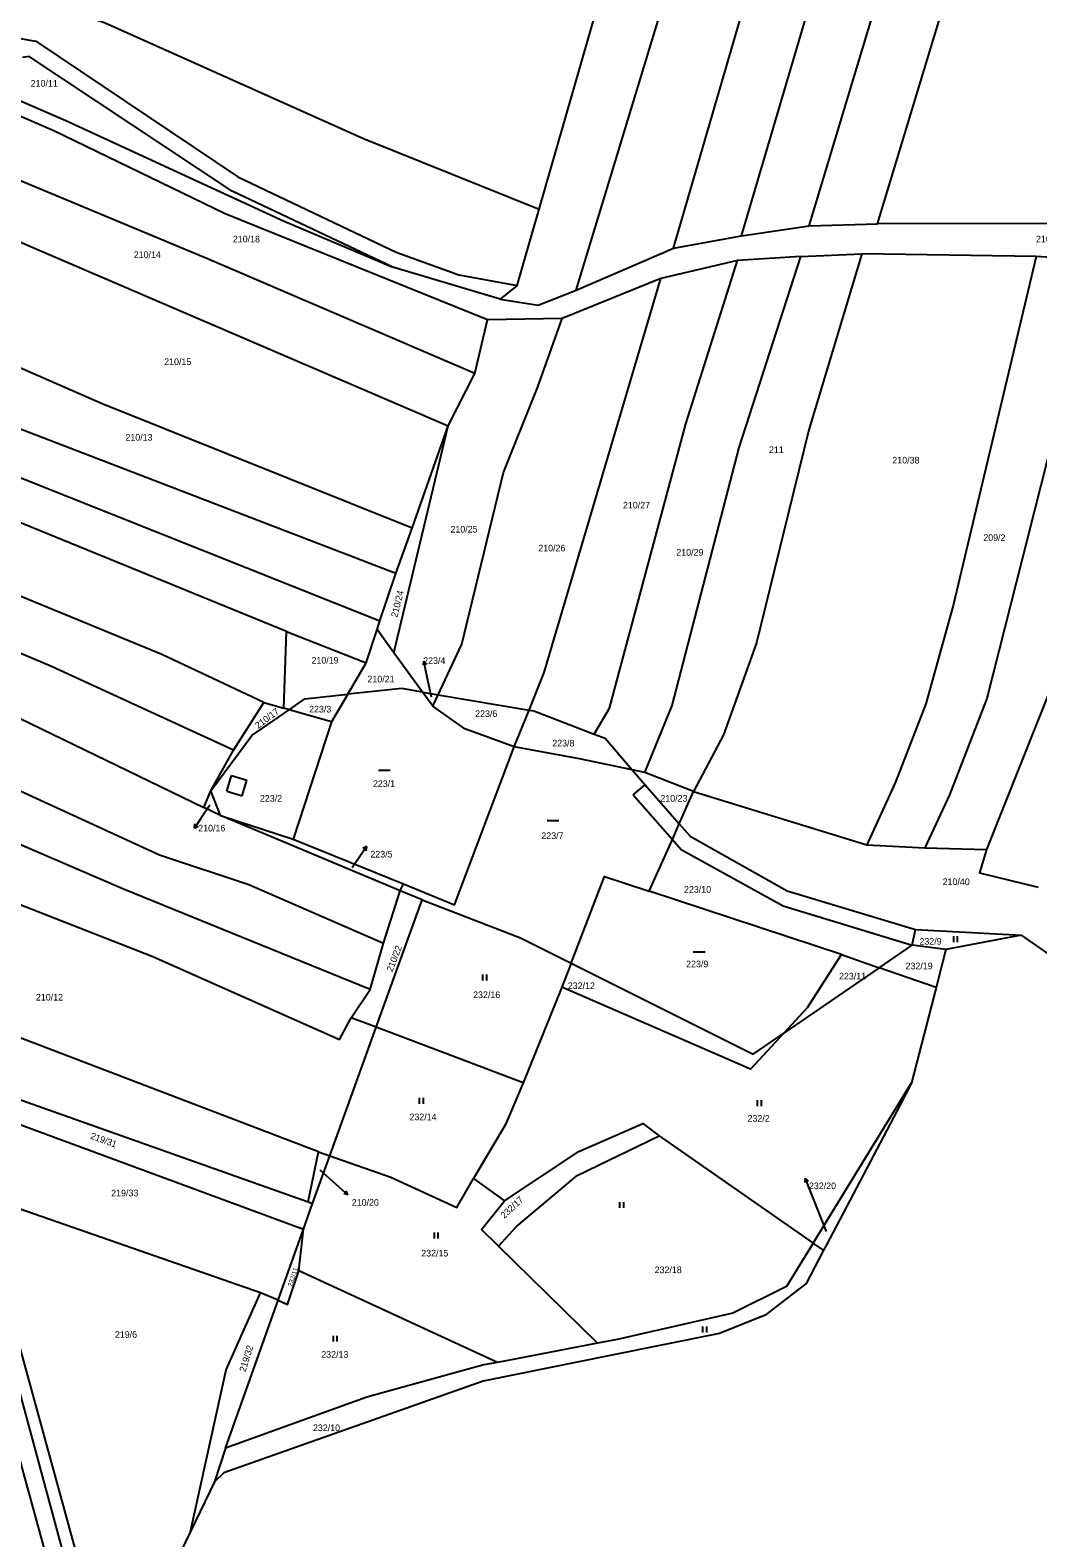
# Model space of a CAD drawing. Extents: x -744566 to -741843, y -1128407 to -1126744.
# Drawn here: x -742757.6 to -742498.8, y -1128024.5 to -1127637.5 of the extents above; entities that cross this region are included whole.
import ezdxf

# ---------------------------------------------------------------- set-up
doc = ezdxf.new("R2010")
doc.units = 0
for name, color, linetype in [('Hranice parcel', 7, 'Continuous'), ('Parcelní čísla', 7, 'Continuous'), ('Pop  PČ popisy', 7, 'Continuous'), ('Vnitřní kresba', 7, 'Continuous'), ('Značky kultur', 7, 'Continuous')]:
    doc.layers.add(name, color=color, linetype=linetype)

msp = doc.modelspace()

# ---------------------------------------------------------------- linework, layer by layer
at = {"layer": 'Hranice parcel'}
for p, q in [((-742626.86, -1127683.46), (-742607.54, -1127616.24)), ((-742632.48, -1127703.04), (-742626.86, -1127683.46)), ((-742574.91, -1127690.26), (-742557.53, -1127687.75)), ((-742557.53, -1127687.75), (-742539.98, -1127687.22)), ((-742494, -1127687.08), (-742539.98, -1127687.22)), ((-742592.33, -1127693.42), (-742574.91, -1127690.26)), ((-742617.34, -1127704.25), (-742592.33, -1127693.42)), ((-742559.67, -1127695.56), (-742575.9, -1127696.61)), ((-742559.67, -1127695.56), (-742544.01, -1127694.88)), ((-742499.23, -1127695.56), (-742544.01, -1127694.88)), ((-742483.38, -1127696.63), (-742499.23, -1127695.56)), ((-742636.82, -1127706.57), (-742664.42, -1127698.33)), ((-742575.9, -1127696.61), (-742595.59, -1127701.21)), ((-742632.48, -1127703.04), (-742636.82, -1127706.57)), ((-742595.59, -1127701.21), (-742620.93, -1127711.51)), ((-742643.36, -1127725.63), (-742640.13, -1127711.82)), ((-742620.93, -1127711.51), (-742640.13, -1127711.82)), ((-742650.2, -1127739.03), (-742643.36, -1127725.63)), ((-742663.65, -1127776.96), (-742792.35, -1127727.57)), ((-742664.19, -1127797.36), (-742650.2, -1127739.03)), ((-742659.43, -1127765.34), (-742650.2, -1127739.03)), ((-742663.65, -1127776.96), (-742659.43, -1127765.34)), ((-742667.79, -1127789.16), (-742663.65, -1127776.96)), ((-742692.45, -1127811.55), (-742691.75, -1127791.9)), ((-742691.75, -1127791.9), (-742671.24, -1127799.9)), ((-742671.24, -1127799.9), (-742668.48, -1127791.31)), ((-742668.48, -1127791.31), (-742667.79, -1127789.16)), ((-742664.19, -1127797.36), (-742668.48, -1127791.31)), ((-742675.99, -1127807.99), (-742671.24, -1127799.9)), ((-742656.82, -1127807.4), (-742664.19, -1127797.36)), ((-742675.99, -1127807.99), (-742680.15, -1127815.09)), ((-742656.82, -1127807.4), (-742652.76, -1127808.09)), ((-742654.13, -1127811.06), (-742656.82, -1127807.4)), ((-742654.13, -1127811.06), (-742652.76, -1127808.09)), ((-742652.76, -1127808.09), (-742629.43, -1127812.04)), ((-742705.33, -1127822.31), (-742697.57, -1127810.08)), ((-742697.57, -1127810.08), (-742692.45, -1127811.55)), ((-742691.07, -1127811.95), (-742692.45, -1127811.55)), ((-742680.15, -1127815.09), (-742691.07, -1127811.95)), ((-742633.23, -1127821.48), (-742629.43, -1127812.04)), ((-742680.15, -1127815.09), (-742690.04, -1127845.16)), ((-742711.14, -1127832.79), (-742705.33, -1127822.31)), ((-742599.71, -1127828.08), (-742602.93, -1127827.4)), ((-742587.17, -1127832.97), (-742599.71, -1127828.08)), ((-742712.92, -1127837.01), (-742711.14, -1127832.79)), ((-742708.67, -1127839.06), (-742711.14, -1127832.79)), ((-742590.87, -1127841.26), (-742587.17, -1127832.97)), ((-742587.17, -1127832.97), (-742542.71, -1127846.65)), ((-742708.67, -1127839.06), (-742712.92, -1127837.01)), ((-742662.54, -1127858.41), (-742708.67, -1127839.06)), ((-742708.67, -1127839.06), (-742690.04, -1127845.16)), ((-742690.04, -1127845.16), (-742661.69, -1127856.62)), ((-742542.71, -1127846.65), (-742527.8, -1127847.44)), ((-742527.8, -1127847.44), (-742511.96, -1127847.84)), ((-742666.84, -1127871.89), (-742662.54, -1127858.41)), ((-742662.54, -1127858.41), (-742661.69, -1127856.62)), ((-742656.86, -1127860.79), (-742662.54, -1127858.41)), ((-742549.19, -1127874.82), (-742598.57, -1127858.52)), ((-742668.67, -1127893.45), (-742656.86, -1127860.79)), ((-742531.05, -1127872.36), (-742530.23, -1127868.37)), ((-742530.23, -1127868.37), (-742503.01, -1127869.85)), ((-742503.01, -1127869.85), (-742522.38, -1127873.53)), ((-742491.5, -1127877.75), (-742503.01, -1127869.85)), ((-742670.28, -1127883.77), (-742666.84, -1127871.89)), ((-742539.51, -1127878.17), (-742531.05, -1127872.36)), ((-742522.38, -1127873.53), (-742531.05, -1127872.36)), ((-742522.38, -1127873.53), (-742524.88, -1127883.24)), ((-742618.61, -1127876.98), (-742620.99, -1127883.17)), ((-742549.19, -1127874.82), (-742539.51, -1127878.17)), ((-742539.51, -1127878.17), (-742564.03, -1127895.02)), ((-742524.88, -1127883.24), (-742539.51, -1127878.17)), ((-742675.1, -1127891.02), (-742670.28, -1127883.77)), ((-742620.99, -1127883.17), (-742630.99, -1127907.7)), ((-742524.88, -1127883.24), (-742531.2, -1127907.76)), ((-742668.67, -1127893.45), (-742675.1, -1127891.02)), ((-742802.25, -1127897.14), (-742686.17, -1127938.31)), ((-742680.6, -1127926.45), (-742668.67, -1127893.45)), ((-742630.99, -1127907.7), (-742668.67, -1127893.45)), ((-742795.76, -1127905.39), (-742687.4, -1127945.34)), ((-742556.49, -1127948.86), (-742531.2, -1127907.76)), ((-742531.2, -1127907.76), (-742534.15, -1127913.36)), ((-742534.15, -1127913.36), (-742553.06, -1127949.33)), ((-742596.01, -1127921.34), (-742556.49, -1127948.86)), ((-742686.17, -1127938.31), (-742683.5, -1127925.44)), ((-742685.04, -1127938.71), (-742680.6, -1127926.45)), ((-742683.5, -1127925.44), (-742680.6, -1127926.45)), ((-742698.39, -1127961.68), (-742775.86, -1127934.72)), ((-742643.67, -1127932.31), (-742635.75, -1127937.99)), ((-742687.4, -1127945.34), (-742685.04, -1127938.71)), ((-742686.17, -1127938.31), (-742685.04, -1127938.71)), ((-742693.88, -1127963.5), (-742687.4, -1127945.34)), ((-742688.57, -1127956.03), (-742687.4, -1127945.34)), ((-742611.87, -1127974.55), (-742637.32, -1127949.65)), ((-742553.8, -1127950.73), (-742556.49, -1127948.86)), ((-742553.06, -1127949.33), (-742553.8, -1127950.73)), ((-742637.54, -1127979.49), (-742688.57, -1127956.03)), ((-742693.88, -1127963.5), (-742698.39, -1127961.68)), ((-742707.43, -1128001.51), (-742693.88, -1127963.5)), ((-742611.87, -1127974.55), (-742637.54, -1127979.49)), ((-742580.51, -1127972.05), (-742608.61, -1127977.73)), ((-742641.25, -1127984.32), (-742707.81, -1128007.87)), ((-742707.43, -1128001.51), (-742710.24, -1128010.19)), ((-742707.81, -1128007.87), (-742710.24, -1128010.19)), ((-742710.24, -1128010.19), (-742716.39, -1128022.92)), ((-742716.39, -1128022.92), (-742728.18, -1128047.33))]:
    msp.add_line(p, q, dxfattribs=at)
for points in [[(-742617.34, -1127704.25), (-742592.59, -1127622.78), (-742562.59, -1127531.26), (-742547.11, -1127485.27), (-742537.81, -1127453.81)], [(-742592.33, -1127693.42), (-742553.24, -1127559.15), (-742522.49, -1127456.7)], [(-742574.91, -1127690.26), (-742552.84, -1127615.42), (-742521.15, -1127514.67), (-742507.28, -1127471.86), (-742504.84, -1127459.15)], [(-742557.53, -1127687.75), (-742527.44, -1127588.04), (-742499.87, -1127499.13), (-742487.9, -1127462.57)], [(-742539.98, -1127687.22), (-742509.38, -1127586.29), (-742471.63, -1127465.86)], [(-742842.01, -1127594.12), (-742781.53, -1127620.27), (-742738.25, -1127635.58), (-742671.97, -1127665.27), (-742626.86, -1127683.46)], [(-742849.54, -1127613.47), (-742848.76, -1127613.6), (-742786.4, -1127635.17), (-742756.11, -1127640.29), (-742704.21, -1127675.14), (-742663.56, -1127694.46), (-742647.49, -1127700.26), (-742632.48, -1127703.04)], [(-742664.42, -1127698.33), (-742705.7, -1127678.8), (-742757.77, -1127644.27), (-742759.53, -1127644.48)], [(-742763.36, -1127654.17), (-742748.4, -1127660.64), (-742692.32, -1127686.56), (-742664.42, -1127698.33)], [(-742640.13, -1127711.82), (-742707.48, -1127684.6), (-742751.48, -1127663.32), (-742764.73, -1127657.63)], [(-742643.36, -1127725.63), (-742711.98, -1127696.17), (-742770.35, -1127671.87)], [(-742775.45, -1127684.77), (-742763.82, -1127690.28), (-742650.2, -1127739.03)], [(-742599.71, -1127828.08), (-742592.67, -1127810.85), (-742575.45, -1127744.63), (-742559.67, -1127695.56)], [(-742544.01, -1127694.88), (-742557.6, -1127740.07), (-742564.08, -1127766.54), (-742571.03, -1127794.76), (-742579.48, -1127818.4), (-742587.17, -1127832.97)], [(-742499.23, -1127695.56), (-742520.53, -1127785.2), (-742527.52, -1127810.4), (-742535.44, -1127830.74), (-742542.71, -1127846.65)], [(-742612.72, -1127818.18), (-742608.79, -1127811.54), (-742589.16, -1127738.55), (-742575.9, -1127696.61)], [(-742483.38, -1127696.63), (-742499.62, -1127760.84), (-742511.87, -1127809.1), (-742521.5, -1127833.81), (-742527.8, -1127847.44)], [(-742467.04, -1127697.67), (-742480.9, -1127748.82), (-742494.32, -1127803.6), (-742511.96, -1127847.84)], [(-742629.43, -1127812.04), (-742625.54, -1127802.36), (-742595.59, -1127701.21)], [(-742878.82, -1127704.23), (-742859.56, -1127712.24), (-742858.85, -1127709.24), (-742793.05, -1127739.22), (-742667.79, -1127789.16)], [(-742636.82, -1127706.57), (-742627.13, -1127708.08), (-742617.34, -1127704.25)], [(-742691.75, -1127791.9), (-742786.9, -1127753.03), (-742859.54, -1127721.45), (-742886.72, -1127710.02)], [(-742659.43, -1127765.34), (-742739.02, -1127733.43), (-742786.49, -1127712.73)], [(-742652.76, -1127808.09), (-742646.74, -1127795.08), (-742636.01, -1127751.08), (-742627.15, -1127729.06), (-742620.93, -1127711.51)], [(-742697.57, -1127810.08), (-742723.74, -1127797.75), (-742779.52, -1127774.85), (-742849.36, -1127744.61), (-742849.6, -1127747), (-742896.29, -1127726.42), (-742905.07, -1127723.45)], [(-742705.33, -1127822.31), (-742752.11, -1127800.85), (-742855.88, -1127756.96), (-742856.57, -1127758.28), (-742916.95, -1127732.14)], [(-742929.76, -1127741.52), (-742892.25, -1127757.26), (-742839.56, -1127779.37), (-742839.56, -1127777.92), (-742777.16, -1127805.95), (-742712.92, -1127837.01)], [(-742942.9, -1127751.14), (-742921.78, -1127760.46), (-742847.12, -1127793.15), (-742812.02, -1127809), (-742724.3, -1127849.19), (-742701.43, -1127856.81), (-742666.84, -1127871.89)], [(-742670.28, -1127883.77), (-742733.59, -1127858.01), (-742796.71, -1127830.89), (-742912.22, -1127779.41), (-742955.04, -1127760.03)], [(-742691.07, -1127811.95), (-742687.04, -1127809.18), (-742675.99, -1127807.99)], [(-742656.82, -1127807.4), (-742662.11, -1127806.5), (-742675.99, -1127807.99)], [(-742711.14, -1127832.79), (-742700.65, -1127818.54), (-742691.07, -1127811.95)], [(-742633.23, -1127821.48), (-742645.94, -1127816.84), (-742654.13, -1127811.06)], [(-742629.43, -1127812.04), (-742628.23, -1127812.24), (-742612.72, -1127818.18)], [(-742612.72, -1127818.18), (-742609.89, -1127819.27), (-742602.93, -1127827.4)], [(-742661.69, -1127856.62), (-742648.57, -1127862.05), (-742633.23, -1127821.48)], [(-742602.93, -1127827.4), (-742616.47, -1127824.52), (-742633.23, -1127821.48)], [(-742602.93, -1127827.4), (-742599.66, -1127831.22), (-742590.87, -1127841.26)], [(-742833.19, -1127833.4), (-742726.08, -1127875.32), (-742678.13, -1127896.57), (-742675.1, -1127891.02)], [(-742598.57, -1127858.52), (-742592.64, -1127845.23), (-742590.87, -1127841.26)], [(-742590.87, -1127841.26), (-742588.09, -1127844.43), (-742563.17, -1127858.44), (-742530.23, -1127868.37)], [(-742511.96, -1127847.84), (-742513.81, -1127853.78), (-742498.72, -1127857.52)], [(-742618.61, -1127876.98), (-742610.06, -1127854.73), (-742598.57, -1127858.52)], [(-742656.86, -1127860.79), (-742631.6, -1127870.48), (-742618.61, -1127876.98)], [(-742683.5, -1127925.44), (-742813.75, -1127875.71), (-742817.94, -1127875.01)], [(-742618.61, -1127876.98), (-742571.86, -1127900.4), (-742564.03, -1127895.02)], [(-742564.03, -1127895.02), (-742557.92, -1127888.41), (-742549.19, -1127874.82)], [(-742564.03, -1127895.02), (-742572.56, -1127904.25), (-742620.99, -1127883.17)], [(-742630.99, -1127907.7), (-742635.51, -1127918.42), (-742643.67, -1127932.31)], [(-742635.75, -1127937.99), (-742616.69, -1127925.34), (-742600.23, -1127918.18), (-742596.01, -1127921.34)], [(-742637.32, -1127949.65), (-742632.63, -1127944.62), (-742617.12, -1127931.51), (-742596.01, -1127921.34)], [(-742680.6, -1127926.45), (-742664.9, -1127931.91), (-742648.02, -1127939.7), (-742643.67, -1127932.31)], [(-742775.86, -1127934.72), (-742770.7, -1127945.05), (-742763.59, -1127963.24), (-742744.12, -1128034.5), (-742737.18, -1128060.8)], [(-742637.32, -1127949.65), (-742641.69, -1127945.38), (-742635.75, -1127937.99)], [(-742556.49, -1127948.86), (-742563.33, -1127959.98), (-742577.15, -1127966.9), (-742606.85, -1127973.58), (-742611.87, -1127974.55)], [(-742553.8, -1127950.73), (-742558.28, -1127959.25), (-742568.84, -1127967.38), (-742580.51, -1127972.05)], [(-742693.88, -1127963.5), (-742691.48, -1127964.62), (-742688.57, -1127956.03)], [(-742716.39, -1128022.92), (-742707.26, -1127981.44), (-742698.39, -1127961.68)], [(-742608.61, -1127977.73), (-742632.32, -1127982.52), (-742641.25, -1127984.32)], [(-742637.54, -1127979.49), (-742641.03, -1127980.16), (-742671.12, -1127988.44), (-742707.43, -1128001.51)]]:
    msp.add_lwpolyline(points, dxfattribs=at)
at = {"layer": 'Pop  PČ popisy'}
for p, q in [((-742656.464, -1127799.455), (-742656.746, -1127800.538)), ((-742655.84, -1127802.39), (-742656.464, -1127799.455)), ((-742656.464, -1127799.455), (-742655.766, -1127800.33)), ((-742654.53, -1127808.7), (-742655.84, -1127802.39)), ((-742711.38, -1127836.41), (-742713.71, -1127839.86)), ((-742713.71, -1127839.86), (-742715.388, -1127842.348)), ((-742715.388, -1127842.348), (-742715.243, -1127841.238)), ((-742715.388, -1127842.348), (-742714.413, -1127841.798)), ((-742674.85, -1127852.46), (-742672.86, -1127849.53)), ((-742672.86, -1127849.53), (-742671.182, -1127847.042)), ((-742671.182, -1127847.042), (-742672.157, -1127847.592)), ((-742671.182, -1127847.042), (-742671.327, -1127848.152)), ((-742683.2, -1127930.09), (-742678.21, -1127934.48)), ((-742678.21, -1127934.48), (-742675.945, -1127936.449)), ((-742675.945, -1127936.449), (-742676.372, -1127935.414)), ((-742558.564, -1127932.198), (-742558.653, -1127933.314)), ((-742557.44, -1127934.98), (-742558.564, -1127932.198)), ((-742558.564, -1127932.198), (-742557.725, -1127932.938)), ((-742553.07, -1127945.89), (-742557.44, -1127934.98)), ((-742675.945, -1127936.449), (-742677.029, -1127936.17))]:
    msp.add_line(p, q, dxfattribs=at)
at = {"layer": 'Vnitřní kresba'}
for p, q in [((-742707.09, -1127832.82), (-742705.88, -1127828.82)), ((-742705.88, -1127828.82), (-742701.93, -1127830.01)), ((-742703.14, -1127834.01), (-742701.93, -1127830.01)), ((-742602.7, -1127833.78), (-742599.66, -1127831.22)), ((-742707.09, -1127832.82), (-742703.14, -1127834.01)), ((-742602.7, -1127833.78), (-742592.64, -1127845.23)), ((-742592.64, -1127845.23), (-742590.38, -1127847.8)), ((-742590.38, -1127847.8), (-742564.19, -1127862.31)), ((-742564.19, -1127862.31), (-742531.05, -1127872.36)), ((-742771.04, -1127965.41), (-742742.76, -1128067.85)), ((-742766.43, -1127964.48), (-742738.98, -1128066.02))]:
    msp.add_line(p, q, dxfattribs=at)
at = {"layer": 'Značky kultur'}
for p, q in [((-742668.108, -1127827.45), (-742665.108, -1127827.45)), ((-742624.808, -1127840.39), (-742621.808, -1127840.39)), ((-742520.381, -1127871.59), (-742520.381, -1127870.09)), ((-742519.38, -1127871.59), (-742519.38, -1127870.09)), ((-742587.258, -1127874.09), (-742584.258, -1127874.09)), ((-742641.301, -1127881.42), (-742641.301, -1127879.92)), ((-742640.3, -1127881.42), (-742640.3, -1127879.92)), ((-742657.551, -1127913.08), (-742657.551, -1127911.58)), ((-742656.55, -1127913.08), (-742656.55, -1127911.58)), ((-742570.771, -1127913.71), (-742570.771, -1127912.21)), ((-742569.77, -1127913.71), (-742569.77, -1127912.21)), ((-742606.131, -1127939.86), (-742606.131, -1127938.36)), ((-742605.13, -1127939.86), (-742605.13, -1127938.36)), ((-742653.751, -1127947.69), (-742653.751, -1127946.19)), ((-742652.75, -1127947.69), (-742652.75, -1127946.19)), ((-742584.821, -1127971.81), (-742584.821, -1127970.31)), ((-742583.82, -1127971.81), (-742583.82, -1127970.31)), ((-742679.691, -1127974.16), (-742679.691, -1127972.66)), ((-742678.69, -1127974.16), (-742678.69, -1127972.66))]:
    msp.add_line(p, q, dxfattribs=at)

# ---------------------------------------------------------------- texts
at = {"layer": 'Parcelní čísla'}
for s, p in [('210/11', (-742757.42, -1127652)), ('210/18', (-742705.5, -1127691.97)), ('210/41', (-742499.26, -1127691.95)), ('210/14', (-742730.94, -1127695.96)), ('210/15', (-742723.13, -1127723.46)), ('210/13', (-742733.08, -1127742.86)), ('211', (-742567.83, -1127746.04)), ('210/38', (-742536.15, -1127748.73)), ('210/27', (-742605.32, -1127760.28)), ('210/25', (-742649.62, -1127766.46)), ('210/26', (-742627.07, -1127771.3)), ('209/2', (-742512.79, -1127768.61)), ('210/29', (-742591.62, -1127772.38)), ('210/19', (-742685.31, -1127800.1)), ('223/4', (-742656.63, -1127800.193)), ('210/21', (-742670.93, -1127804.93)), ('223/3', (-742685.92, -1127812.65)), ('223/6', (-742643.28, -1127813.81)), ('223/8', (-742623.48, -1127821.38)), ('223/1', (-742669.52, -1127831.77)), ('223/2', (-742698.55, -1127835.55)), ('210/23', (-742595.72, -1127835.54)), ('210/16', (-742714.39, -1127843.19)), ('223/7', (-742626.28, -1127845.15)), ('223/5', (-742670.18, -1127849.883)), ('223/10', (-742589.65, -1127858.92)), ('210/40', (-742523.24, -1127856.97)), ('232/9', (-742529.193, -1127872.27)), ('223/9', (-742589.1, -1127878.05)), ('232/19', (-742532.75, -1127878.57)), ('223/11', (-742549.84, -1127881.19)), ('210/12', (-742756.07, -1127886.6)), ('232/16', (-742643.8, -1127885.98)), ('232/12', (-742619.49, -1127883.66)), ('232/14', (-742660.14, -1127917.33)), ('232/2', (-742573.34, -1127917.7)), ('219/33', (-742736.74, -1127936.87)), ('232/20', (-742557.56, -1127935.023)), ('210/20', (-742674.96, -1127939.293)), ('232/15', (-742657.12, -1127952.31)), ('232/18', (-742597.19, -1127956.59)), ('219/6', (-742735.79, -1127973.19)), ('232/13', (-742682.79, -1127978.29)), ('232/10', (-742684.93, -1127997.14))]:
    msp.add_text(s, height=1.7, dxfattribs=at).set_placement(p)
for s, height, rotation, p in [('210/24', 1.7, 76, (-742663.275, -1127788.345)), ('210/17', 1.7, 37, (-742698.998, -1127816.928)), ('210/22', 1.7, 69, (-742664.536, -1127879.364)), ('219/31', 1.7, 340, (-742742.21, -1127922.018)), ('232/17', 1.7, 43, (-742635.81, -1127942.691)), ('232/11', 1.19, 72, (-742690.314, -1127960.133)), ('219/32', 1.7, 73, (-742702.257, -1127982.068))]:
    msp.add_text(s, height=height, rotation=rotation, dxfattribs=at).set_placement(p)

doc.saveas('drawing.dxf')
